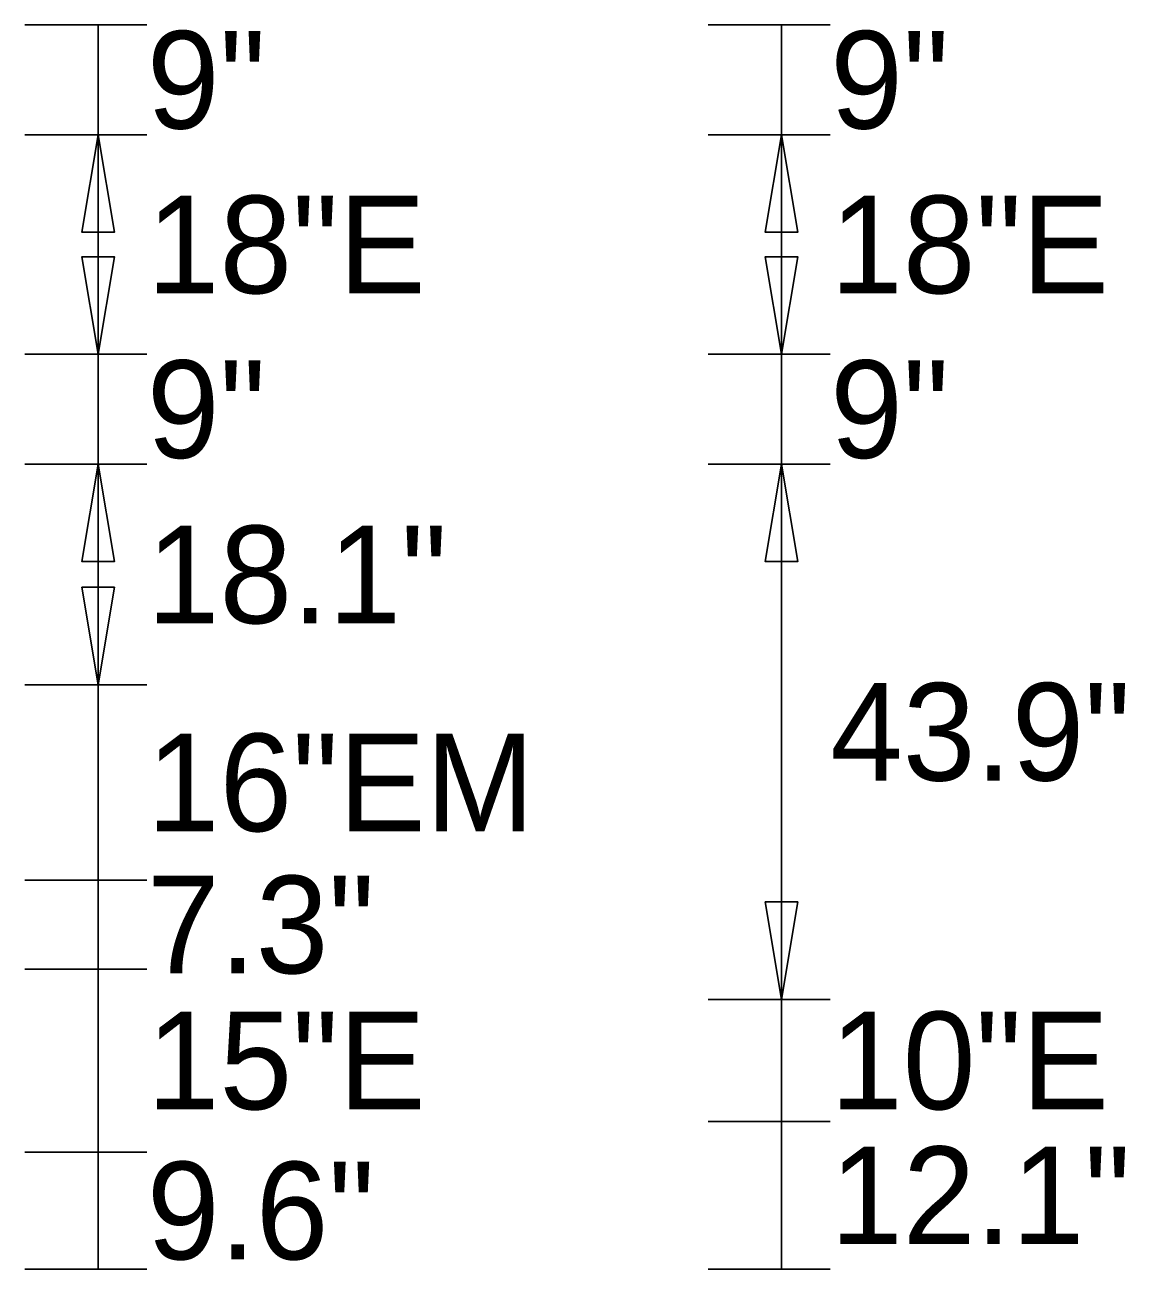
# Model space of a CAD drawing. Extents: x 2149961 to 2150220, y 145114 to 145240.
# Drawn here: x 2149996.08 to 2150003.59, y 145193.01 to 145201.51 of the extents above; entities that cross this region are included whole.
import ezdxf

# ---------------------------------------------------------------- set-up
doc = ezdxf.new("R2010")
doc.units = 0
doc.layers.add('GSDIMS', color=7, linetype='Continuous')

msp = doc.modelspace()

# ---------------------------------------------------------------- linework, layer by layer
at = {"layer": 'GSDIMS'}
for p, q in [((2149996.075, 145201.5094), (2149996.9083, 145201.5094)), ((2149996.575, 145200.7591), (2149996.575, 145201.5094)), ((2150000.7417, 145201.5094), (2150001.575, 145201.5094)), ((2150001.2417, 145200.7591), (2150001.2417, 145201.5094)), ((2149996.075, 145200.7591), (2149996.9083, 145200.7591)), ((2149996.075, 145200.7591), (2149996.9083, 145200.7591)), ((2149996.575, 145200.7591), (2149996.575, 145199.2591)), ((2150000.7417, 145200.7591), (2150001.575, 145200.7591)), ((2150000.7417, 145200.7591), (2150001.575, 145200.7591)), ((2150001.2417, 145200.7591), (2150001.2417, 145199.2591)), ((2149996.075, 145199.2591), (2149996.9083, 145199.2591)), ((2149996.075, 145199.2591), (2149996.9083, 145199.2591)), ((2149996.575, 145198.5087), (2149996.575, 145199.2591)), ((2150000.7417, 145199.2591), (2150001.575, 145199.2591)), ((2150000.7417, 145199.2591), (2150001.575, 145199.2591)), ((2150001.2417, 145198.5087), (2150001.2417, 145199.2591)), ((2149996.075, 145198.5088), (2149996.9083, 145198.5088)), ((2149996.075, 145198.5087), (2149996.9083, 145198.5087)), ((2149996.575, 145197.0005), (2149996.575, 145198.5088)), ((2150000.7417, 145198.5088), (2150001.575, 145198.5088)), ((2150000.7417, 145198.5087), (2150001.575, 145198.5087)), ((2150001.2417, 145194.8505), (2150001.2417, 145198.5088)), ((2149996.075, 145197.0005), (2149996.9083, 145197.0005)), ((2149996.075, 145197.0005), (2149996.9083, 145197.0005)), ((2149996.575, 145197.0005), (2149996.575, 145195.6671)), ((2149996.075, 145195.6671), (2149996.9083, 145195.6671)), ((2149996.075, 145195.6671), (2149996.9083, 145195.6671)), ((2149996.575, 145195.0588), (2149996.575, 145195.6671)), ((2149996.075, 145195.0588), (2149996.9083, 145195.0588)), ((2149996.075, 145195.0588), (2149996.9083, 145195.0588)), ((2149996.575, 145195.0588), (2149996.575, 145193.8088)), ((2150000.7417, 145194.8505), (2150001.575, 145194.8505)), ((2150000.7417, 145194.8505), (2150001.575, 145194.8505)), ((2150001.2417, 145194.8505), (2150001.2417, 145194.0171)), ((2150000.7417, 145194.0171), (2150001.575, 145194.0171)), ((2150000.7417, 145194.0171), (2150001.575, 145194.0171)), ((2150001.2417, 145193.0087), (2150001.2417, 145194.0171)), ((2149996.075, 145193.8088), (2149996.9083, 145193.8088)), ((2149996.075, 145193.8088), (2149996.9083, 145193.8088)), ((2149996.575, 145193.0087), (2149996.575, 145193.8088)), ((2149996.075, 145193.0087), (2149996.9083, 145193.0087)), ((2150000.7417, 145193.0087), (2150001.575, 145193.0087))]:
    msp.add_line(p, q, dxfattribs=at)
for points in [[(2149996.575, 145200.7591), (2149996.4639, 145200.0924), (2149996.6861, 145200.0924)], [(2150001.2417, 145200.7591), (2150001.1306, 145200.0924), (2150001.3528, 145200.0924)], [(2149996.575, 145199.2591), (2149996.4639, 145199.9257), (2149996.6861, 145199.9257)], [(2150001.2417, 145199.2591), (2150001.1306, 145199.9257), (2150001.3528, 145199.9257)], [(2149996.575, 145198.5088), (2149996.4639, 145197.8421), (2149996.6861, 145197.8421)], [(2150001.2417, 145198.5088), (2150001.1306, 145197.8421), (2150001.3528, 145197.8421)], [(2149996.575, 145197.0005), (2149996.4639, 145197.6671), (2149996.6861, 145197.6671)], [(2150001.2417, 145194.8505), (2150001.1306, 145195.5171), (2150001.3528, 145195.5171)]]:
    msp.add_lwpolyline(points, close=True, dxfattribs=at)

# ---------------------------------------------------------------- texts
for s, p in [('9"', (2149996.9084, 145200.8009)), ('9"', (2150001.575, 145200.8009)), ('18"E', (2149996.9084, 145199.6757)), ('18"E', (2150001.575, 145199.6757)), ('9"', (2149996.9084, 145198.5506)), ('9"', (2150001.575, 145198.5506)), ('18.1"', (2149996.9084, 145197.4213)), ('43.9"', (2150001.575, 145196.3463)), ('16"EM', (2149996.9084, 145196.0004)), ('7.3"', (2149996.9084, 145195.0296)), ('15"E', (2149996.9084, 145194.1005)), ('10"E', (2150001.575, 145194.1005)), ('12.1"', (2150001.575, 145193.1796)), ('9.6"', (2149996.9084, 145193.0754))]:
    msp.add_text(s, height=0.66667, dxfattribs=at).set_placement(p)

doc.saveas('drawing.dxf')
